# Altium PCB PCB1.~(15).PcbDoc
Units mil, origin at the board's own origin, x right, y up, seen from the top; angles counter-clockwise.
Board outline 5880 x 2260 mil, 2 copper layers (Top Layer, Bottom Layer); 100 components, 175 nets, 425 pads, 117 vias.
Unrouted connection lines stored in the file: 20.
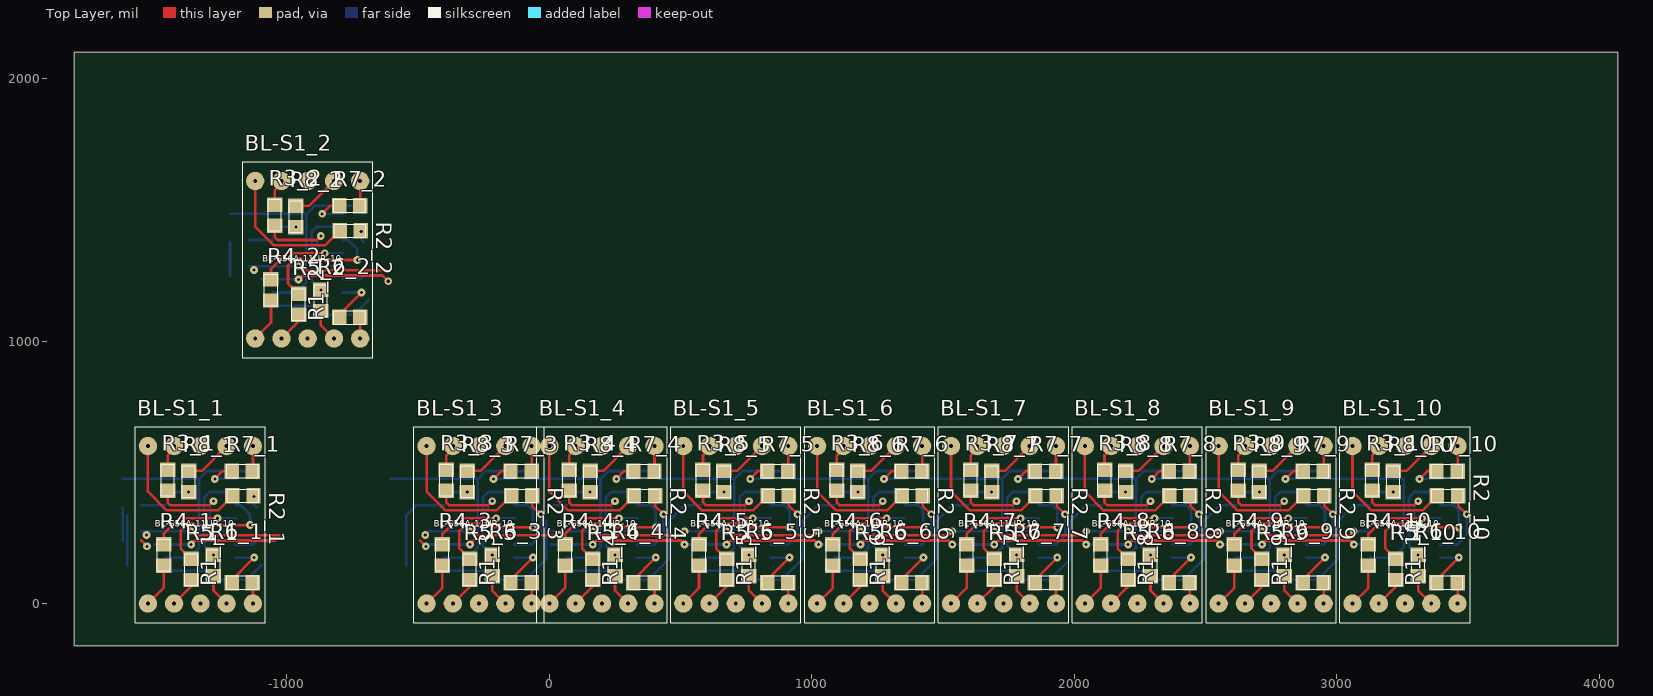
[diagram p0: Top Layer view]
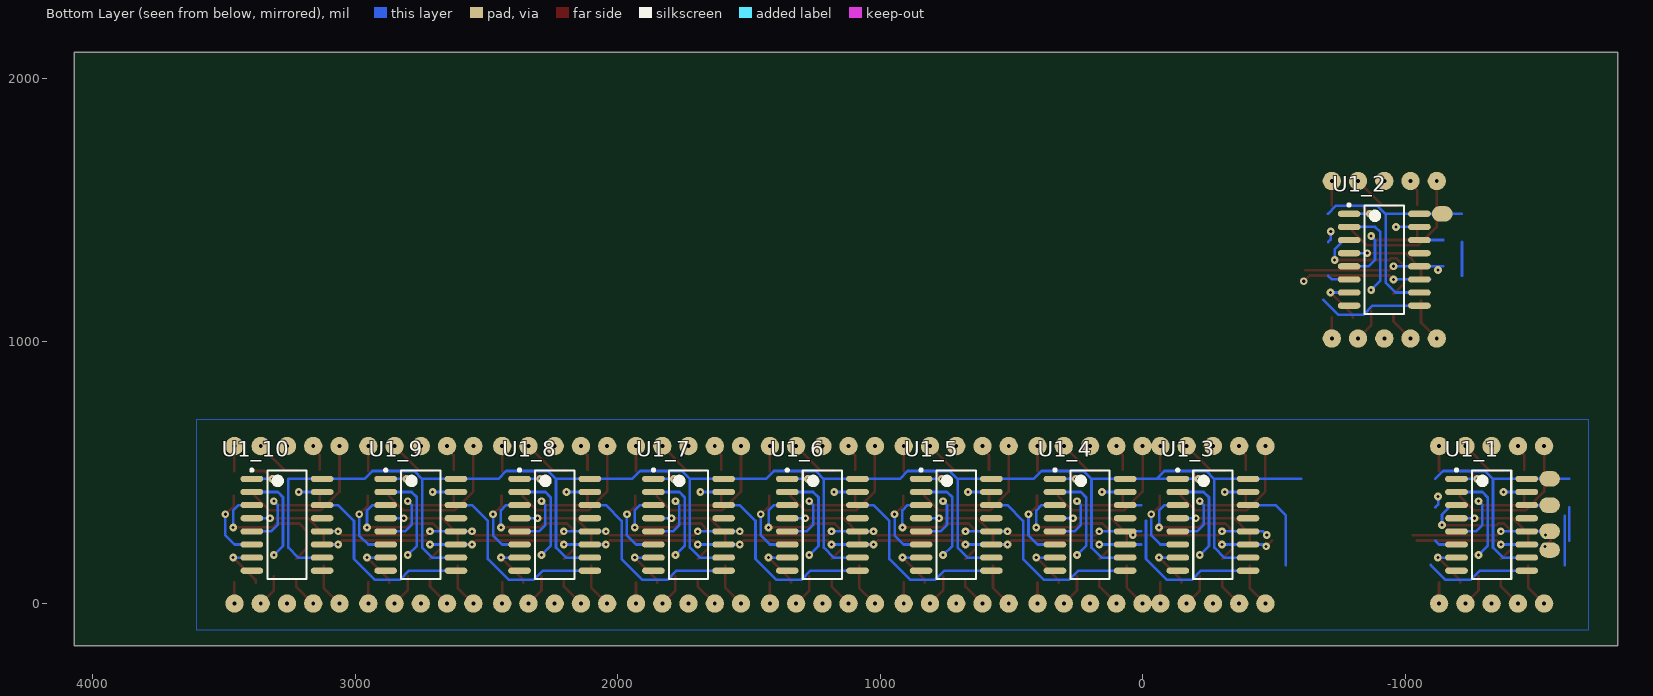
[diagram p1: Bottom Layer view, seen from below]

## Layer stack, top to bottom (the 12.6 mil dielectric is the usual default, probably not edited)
Top Solder: solder mask 0.4, Solder Resist, Dk 3.5
Top Layer: signal copper 1.4
Dielectric 1: dielectric 12.6, FR-4, Dk 4.8
Bottom Layer: signal copper 1.4
Bottom Solder: solder mask 0.4, Solder Resist, Dk 3.5

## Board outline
-1810,-160 -1810,2100 4070,2100 4070,-160 -220,-160

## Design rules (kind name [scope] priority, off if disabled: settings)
Clearance [All] p1: gap=5
MinimumSolderMaskSliver [All] p1 off: minsoldermaskwidth=10
PolygonConnect [All] p1: connectstyle=Relief reliefconductorwidth=10 reliefentries=4 polygonreliefangle="90 Angle" airgapwidth=15
RoomDefinition 10 [InComponentClass('10')] p1: confinementstyle=ConfineIn formatcopy=TRUE lockcomponents=FALSE outline 3005,-100 3600,-100 3600,700 3005,700
RoomDefinition 9 [InComponentClass('9')] p2: confinementstyle=ConfineIn formatcopy=TRUE lockcomponents=FALSE outline 2495,-100 3090,-100 3090,700 2495,700
RoomDefinition 8 [InComponentClass('8')] p3: confinementstyle=ConfineIn formatcopy=TRUE lockcomponents=FALSE outline 1985,-100 2580,-100 2580,700 1985,700
RoomDefinition 7 [InComponentClass('7')] p4: confinementstyle=ConfineIn formatcopy=TRUE lockcomponents=FALSE outline 1475,-100 2070,-100 2070,700 1475,700
RoomDefinition 6 [InComponentClass('6')] p5: confinementstyle=ConfineIn formatcopy=TRUE lockcomponents=FALSE outline 965,-100 1560,-100 1560,700 965,700
RoomDefinition 5 [InComponentClass('5')] p6: confinementstyle=ConfineIn formatcopy=TRUE lockcomponents=FALSE outline 455,-100 1050,-100 1050,700 455,700
RoomDefinition 4 [InComponentClass('4')] p7: confinementstyle=ConfineIn formatcopy=TRUE lockcomponents=FALSE outline -55,-100 540,-100 540,700 -55,700
RoomDefinition 2 [InComponentClass('2')] p8: confinementstyle=ConfineIn formatcopy=TRUE lockcomponents=FALSE outline -1218,910 -581,910 -581,1710 -1218,1710
RoomDefinition 1 [InComponentClass('1')] p9: confinementstyle=ConfineIn formatcopy=TRUE lockcomponents=FALSE outline -1627,-100 -990,-100 -990,700 -1627,700
RoomDefinition 3 [InComponentClass('3')] p10: confinementstyle=ConfineIn formatcopy=TRUE lockcomponents=FALSE outline -565,-100 72,-100 72,700 -565,700
RoutingVias [All] p1: holewidth=11.81 width=29.53 viastyle="Through Hole" minholewidth=11.81 minwidth=29.53 maxholewidth=28 maxwidth=70
SilkToBoardRegionClearance [All] p1 off:
SilkToSilkClearance [All] p1 off: silktosilkclearance=10
SilkToSolderMaskClearance [IsPad] p1 off: minsilkscreentomaskgap=10 clearancetoexposedcopper=TRUE
SolderMaskExpansion [All] p1: expansion=4
Width [All] p1: maxlimit=10 minlimit=7.87 preferedwidth=10
26 further rules are at their usual default settings.

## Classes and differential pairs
component class 6: BL-S1_6 R1_6 R2_6 R3_6 R4_6 R5_6 R6_6 R7_6 R8_6 U1_6
component class 5: BL-S1_5 R1_5 R2_5 R3_5 R4_5 R5_5 R6_5 R7_5 R8_5 U1_5
component class 1: BL-S1_1 R1_1 R2_1 R3_1 R4_1 R5_1 R6_1 R7_1 R8_1 U1_1
component class 2: BL-S1_2 R1_2 R2_2 R3_2 R4_2 R5_2 R6_2 R7_2 R8_2 U1_2
component class 3: BL-S1_3 R1_3 R2_3 R3_3 R4_3 R5_3 R6_3 R7_3 R8_3 U1_3
component class 4: BL-S1_4 R1_4 R2_4 R3_4 R4_4 R5_4 R6_4 R7_4 R8_4 U1_4
channel class Sheet2: 1 2 3 4 5 6 7 8 9 10
component class 7: BL-S1_7 R1_7 R2_7 R3_7 R4_7 R5_7 R6_7 R7_7 R8_7 U1_7
component class 8: BL-S1_8 R1_8 R2_8 R3_8 R4_8 R5_8 R6_8 R7_8 R8_8 U1_8
component class 9: BL-S1_9 R1_9 R2_9 R3_9 R4_9 R5_9 R6_9 R7_9 R8_9 U1_9
component class 10: BL-S1_10 R1_10 R2_10 R3_10 R4_10 R5_10 R6_10 R7_10 R8_10 U1_10

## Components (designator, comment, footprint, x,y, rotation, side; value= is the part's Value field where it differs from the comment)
BL-S1_1 "BL-S56A-11UR" BL-S56A-11UR -1578.03,300 r0 top locked (schematic designator BL-S1)
BL-S1_2 "BL-S56A-11UR" BL-S56A-11UR -1169.03,1310 r0 top (schematic designator BL-S1)
BL-S1_3 "BL-S56A-11UR" BL-S56A-11UR -516.03,300 r0 top (schematic designator BL-S1)
BL-S1_4 "BL-S56A-11UR" BL-S56A-11UR -48.03,300 r0 top (schematic designator BL-S1)
BL-S1_5 "BL-S56A-11UR" BL-S56A-11UR 461.97,300 r0 top (schematic designator BL-S1)
BL-S1_6 "BL-S56A-11UR" BL-S56A-11UR 971.97,300 r0 top (schematic designator BL-S1)
BL-S1_7 "BL-S56A-11UR" BL-S56A-11UR 1481.97,300 r0 top (schematic designator BL-S1)
BL-S1_8 "BL-S56A-11UR" BL-S56A-11UR 1991.97,300 r0 top (schematic designator BL-S1)
BL-S1_9 "BL-S56A-11UR" BL-S56A-11UR 2501.97,300 r0 top (schematic designator BL-S1)
BL-S1_10 "BL-S56A-11UR" BL-S56A-11UR 3011.97,300 r0 top (schematic designator BL-S1)
R1_1 "310R" Res0805 -1170,80 r180 top (schematic designator R1)
R1_2 "310R" Res0805 -761,1090 r180 top (schematic designator R1)
R1_3 "310R" Res0805 -108,80 r180 top (schematic designator R1)
R1_4 "310R" Res0805 360,80 r180 top (schematic designator R1)
R1_5 "310R" Res0805 870,80 r180 top (schematic designator R1)
R1_6 "310R" Res0805 1380,80 r180 top (schematic designator R1)
R1_7 "310R" Res0805 1890,80 r180 top (schematic designator R1)
R1_8 "310R" Res0805 2400,80 r180 top (schematic designator R1)
R1_9 "310R" Res0805 2910,80 r180 top (schematic designator R1)
R1_10 "310R" Res0805 3420,80 r180 top (schematic designator R1)
R2_1 "310R" Res0805 -1167.95,410 r0 top (schematic designator R2)
R2_2 "310R" Res0805 -758.95,1420 r0 top (schematic designator R2)
R2_3 "310R" Res0805 -105.95,410 r0 top (schematic designator R2)
R2_4 "310R" Res0805 362.05,410 r0 top (schematic designator R2)
R2_5 "310R" Res0805 872.05,410 r0 top (schematic designator R2)
R2_6 "310R" Res0805 1382.05,410 r0 top (schematic designator R2)
R2_7 "310R" Res0805 1892.05,410 r0 top (schematic designator R2)
R2_8 "310R" Res0805 2402.05,410 r0 top (schematic designator R2)
R2_9 "310R" Res0805 2912.05,410 r0 top (schematic designator R2)
R2_10 "310R" Res0805 3422.05,410 r0 top (schematic designator R2)
R3_1 "310R" Res0805 -1455,470 r270 top (schematic designator R3)
R3_2 "310R" Res0805 -1046,1480 r270 top (schematic designator R3)
R3_3 "310R" Res0805 -393,470 r270 top (schematic designator R3)
R3_4 "310R" Res0805 75,470 r270 top (schematic designator R3)
R3_5 "310R" Res0805 585,470 r270 top (schematic designator R3)
R3_6 "310R" Res0805 1095,470 r270 top (schematic designator R3)
R3_7 "310R" Res0805 1605,470 r270 top (schematic designator R3)
R3_8 "310R" Res0805 2115,470 r270 top (schematic designator R3)
R3_9 "310R" Res0805 2625,470 r270 top (schematic designator R3)
R3_10 "310R" Res0805 3135,470 r270 top (schematic designator R3)
R4_1 "310R" Res0805 -1470,185 r90 top (schematic designator R4)
R4_2 "310R" Res0805 -1061,1195 r90 top (schematic designator R4)
R4_3 "310R" Res0805 -408,185 r90 top (schematic designator R4)
R4_4 "310R" Res0805 60,185 r90 top (schematic designator R4)
R4_5 "310R" Res0805 570,185 r90 top (schematic designator R4)
R4_6 "310R" Res0805 1080,185 r90 top (schematic designator R4)
R4_7 "310R" Res0805 1590,185 r90 top (schematic designator R4)
R4_8 "310R" Res0805 2100,185 r90 top (schematic designator R4)
R4_9 "310R" Res0805 2610,185 r90 top (schematic designator R4)
R4_10 "310R" Res0805 3120,185 r90 top (schematic designator R4)
R5_1 "310R" Res0805 -1365,130 r90 top (schematic designator R5)
R5_2 "310R" Res0805 -956,1140 r90 top (schematic designator R5)
R5_3 "310R" Res0805 -303,130 r90 top (schematic designator R5)
R5_4 "310R" Res0805 165,130 r90 top (schematic designator R5)
R5_5 "310R" Res0805 675,130 r90 top (schematic designator R5)
R5_6 "310R" Res0805 1185,130 r90 top (schematic designator R5)
R5_7 "310R" Res0805 1695,130 r90 top (schematic designator R5)
R5_8 "310R" Res0805 2205,130 r90 top (schematic designator R5)
R5_9 "310R" Res0805 2715,130 r90 top (schematic designator R5)
R5_10 "310R" Res0805 3225,130 r90 top (schematic designator R5)
R6_1 "310R" Res0805 -1280,145 r90 top (schematic designator R6)
R6_2 "310R" Res0805 -871,1155 r90 top (schematic designator R6)
R6_3 "310R" Res0805 -218,145 r90 top (schematic designator R6)
R6_4 "310R" Res0805 250,145 r90 top (schematic designator R6)
R6_5 "310R" Res0805 760,145 r90 top (schematic designator R6)
R6_6 "310R" Res0805 1270,145 r90 top (schematic designator R6)
R6_7 "310R" Res0805 1780,145 r90 top (schematic designator R6)
R6_8 "310R" Res0805 2290,145 r90 top (schematic designator R6)
R6_9 "310R" Res0805 2800,145 r90 top (schematic designator R6)
R6_10 "310R" Res0805 3310,145 r90 top (schematic designator R6)
R7_1 "310R" Res0805 -1170,505 r180 top (schematic designator R7)
R7_2 "310R" Res0805 -761,1515 r180 top (schematic designator R7)
R7_3 "310R" Res0805 -108,505 r180 top (schematic designator R7)
R7_4 "310R" Res0805 360,505 r180 top (schematic designator R7)
R7_5 "310R" Res0805 870,505 r180 top (schematic designator R7)
R7_6 "310R" Res0805 1380,505 r180 top (schematic designator R7)
R7_7 "310R" Res0805 1890,505 r180 top (schematic designator R7)
R7_8 "310R" Res0805 2400,505 r180 top (schematic designator R7)
R7_9 "310R" Res0805 2910,505 r180 top (schematic designator R7)
R7_10 "310R" Res0805 3420,505 r180 top (schematic designator R7)
R8_1 "310R" Res0805 -1375,465 r270 top (schematic designator R8)
R8_2 "310R" Res0805 -966,1475 r270 top (schematic designator R8)
R8_3 "310R" Res0805 -313,465 r270 top (schematic designator R8)
R8_4 "310R" Res0805 155,465 r270 top (schematic designator R8)
R8_5 "310R" Res0805 665,465 r270 top (schematic designator R8)
R8_6 "310R" Res0805 1175,465 r270 top (schematic designator R8)
R8_7 "310R" Res0805 1685,465 r270 top (schematic designator R8)
R8_8 "310R" Res0805 2195,465 r270 top (schematic designator R8)
R8_9 "310R" Res0805 2705,465 r270 top (schematic designator R8)
R8_10 "310R" Res0805 3215,465 r270 top (schematic designator R8)
U1_1 "HD74HC595FP" PRSP0016DH-B_N -1330,300 r180 bottom (schematic designator U1)
U1_2 "HD74HC595FP" PRSP0016DH-B_N -921,1310 r180 bottom (schematic designator U1)
U1_3 "HD74HC595FP" PRSP0016DH-B_N -268,300 r180 bottom (schematic designator U1)
U1_4 "HD74HC595FP" PRSP0016DH-B_N 200,300 r180 bottom (schematic designator U1)
U1_5 "HD74HC595FP" PRSP0016DH-B_N 710,300 r180 bottom (schematic designator U1)
U1_6 "HD74HC595FP" PRSP0016DH-B_N 1220,300 r180 bottom (schematic designator U1)
U1_7 "HD74HC595FP" PRSP0016DH-B_N 1730,300 r180 bottom (schematic designator U1)
U1_8 "HD74HC595FP" PRSP0016DH-B_N 2240,300 r180 bottom (schematic designator U1)
U1_9 "HD74HC595FP" PRSP0016DH-B_N 2750,300 r180 bottom (schematic designator U1)
U1_10 "HD74HC595FP" PRSP0016DH-B_N 3260,300 r180 bottom (schematic designator U1)

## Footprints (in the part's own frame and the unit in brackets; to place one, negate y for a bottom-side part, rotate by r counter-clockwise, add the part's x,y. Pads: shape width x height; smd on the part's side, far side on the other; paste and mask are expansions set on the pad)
BL-S56A-11UR [mil]
  round 70 hole 15: 1(48.03,-300) 2(148.03,-300) 3(248.03,-300) 4(348.03,-300) 5(448.03,-300) 6(448.03,300) 7(348.03,300) 8(248.03,300) 9(148.03,300) 10(48.03,300)
  silkscreen extent 0,-374 496,374, body extent 0,-374 496,374, height 315
PRSP0016DH-B_N [mm] "SOP, 16-Leads, Body 10.06x5.5mm, Pitch 1.27mm, IPC Medium Density"
  oval 2.2x0.6 smd: 1(-3.4,4.445) 2(-3.4,3.175) 3(-3.4,1.905) 4(-3.4,0.635) 5(-3.4,-0.635) 6(-3.4,-1.905) 7(-3.4,-3.175) 8(-3.4,-4.445) 9(3.4,-4.445) 10(3.4,-3.175) 11(3.4,-1.905) 12(3.4,-0.635) 13(3.4,0.635) 14(3.4,1.905) 15(3.4,3.175) 16(3.4,4.445)
  silkscreen extent -3.52,-5.25 1.9,5.42, body extent -2.7,-5.25 2.7,5.25, height 2.2
Res0805 [mm]
  rect 1.4x1.5 smd: 1(-1.025,0) 2(1.025,0)
  silkscreen extent -1.52,-0.64 1.52,0.64, body extent -1.15,-0.67 1.15,0.68, height 0.76

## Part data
BL-S1_1 BL-S1_2 BL-S1_3 BL-S1_4 BL-S1_5 BL-S1_6 BL-S1_7 BL-S1_8 BL-S1_9 BL-S1_10: library part Component_1
R1_1 R1_2 R1_3 R1_4 R1_5 R1_6 R1_7 R1_8 R1_9 R1_10 R2_1 R2_2 R2_3 R2_4 R2_5 R2_6 R2_7 R2_8 R2_9 R2_10 R3_1 R3_2 R3_3 R3_4 R3_5 R3_6 R3_7 R3_8 R3_9 R3_10 R4_1 R4_2 R4_3 R4_4 R4_5 R4_6 R4_7 R4_8 R4_9 R4_10 R5_1 R5_2 R5_3 R5_4 R5_5 R5_6 R5_7 R5_8 R5_9 R5_10 R6_1 R6_2 R6_3 R6_4 R6_5 R6_6 R6_7 R6_8 R6_9 R6_10 R7_1 R7_2 R7_3 R7_4 R7_5 R7_6 R7_7 R7_8 R7_9 R7_10 R8_1 R8_2 R8_3 R8_4 R8_5 R8_6 R8_7 R8_8 R8_9 R8_10: library part Res1, "Resistor"
U1_1 U1_2 U1_3 U1_4 U1_5 U1_6 U1_7 U1_8 U1_9 U1_10: "8-bit Shift Register / Latch with 3-State Outputs"

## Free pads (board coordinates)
  oval 78.74x59.06 smd far side: 8(-1550.94,475) 8(-1141.94,1485) 9(-1550.94,375) 10(-1550.94,275) 11(-1551,204)

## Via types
v1: diameter 29.53, hole 11.81, Top Layer to Bottom Layer, tented both sides, 90 vias
v2: diameter 29.53, hole 11.81, Top Layer to Bottom Layer, 27 vias

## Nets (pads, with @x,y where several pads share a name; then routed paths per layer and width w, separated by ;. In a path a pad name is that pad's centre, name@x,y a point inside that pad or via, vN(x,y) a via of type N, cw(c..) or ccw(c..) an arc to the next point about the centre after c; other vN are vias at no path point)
+5V: pad.8 U1_1.10 U1_1.16 U1_2.10 U1_2.16 U1_3.10 U1_3.16 U1_4.10 U1_4.16 U1_5.10 U1_5.16 U1_6.10 U1_6.16 U1_7.10 U1_7.16 U1_8.10 U1_8.16 U1_9.10 U1_9.16 U1_10.10 U1_10.16 | length 9592.6
  Bottom Layer w10: -1625,475 U1_1.16 ; -1595,475 U1_1.16 ; U1_1.10 -1372.91,175 -1335.24,212.67 -1335.24,475 ; -1216,1485 U1_2.16 ; -1186,1485 U1_2.16 ; -1115,475 -1145,505 -1305,505 -1335,475 U1_1.16 ; U1_2.10 -963.91,1185 -926.24,1222.67 -926.24,1485 ; -706,1485 -736,1515 -896,1515 -926,1485 U1_2.16 ; -605,475 U1_3.16@-443.86,475 ; -563,475 U1_3.16 -273,475 -243,505 -83,505 -53,475 ; U1_3.10 -310.91,175 -273.24,212.67 -273.24,475 ; -95,475 U1_4.16 194.76,475 ; U1_4.10 157.09,175 194.76,212.67 194.76,475 ; U1_5.10 667.09,175 704.76,212.67 704.76,475 ; U1_6.10 1177.09,175 1214.76,212.67 1214.76,475 ; U1_7.10 1687.09,175 1724.76,212.67 1724.76,475 ; U1_8.10 2197.09,175 2234.76,212.67 2234.76,475 ; U1_9.10 2707.09,175 2744.76,212.67 2744.76,475 ; U1_10.10 3217.09,175 3254.76,212.67 3254.76,475 ; 3255,475 3254.76,475 ; 194.76,475 195,475 225,505 385,505 415,475 U1_5.16 704.76,475 ; 704.76,475 705,475 735,505 895,505 925,475 U1_6.16 1214.76,475 ; 1214.76,475 1215,475 1245,505 1405,505 1435,475 U1_7.16 1724.76,475 ; 1724.76,475 1725,475 1755,505 1915,505 1945,475 U1_8.16 2234.76,475 ; 2234.76,475 2235,475 2265,505 2425,505 2455,475 U1_9.16 2744.76,475 ; 2744.76,475 2745,475 2775,505 2935,505 2965,475 U1_10.16 3254.76,475
GND: BL-S1_1.3 BL-S1_1.8 BL-S1_2.3 BL-S1_2.8 BL-S1_3.3 BL-S1_3.8 BL-S1_4.3 BL-S1_4.8 BL-S1_5.3 BL-S1_5.8 BL-S1_6.3 BL-S1_6.8 BL-S1_7.3 BL-S1_7.8 BL-S1_8.3 BL-S1_8.8 BL-S1_9.3 BL-S1_9.8 BL-S1_10.3 BL-S1_10.8 U1_1.8 U1_1.13 U1_2.8 U1_2.13 U1_3.8 U1_3.13 U1_4.8 U1_4.13 U1_5.8 U1_5.13 U1_6.8 U1_6.13 U1_7.8 U1_7.13 U1_8.8 U1_8.13 U1_9.8 U1_9.13 U1_10.8 U1_10.13
L_A_1: BL-S1_1.7 R8_1.1 | length 184.2
  Top Layer w10: R8_1.1 -1324.65,505.35 BL-S1_1.7
L_A_2: BL-S1_2.7 R8_2.1 | length 184.2
  Top Layer w10: R8_2.1 -915.65,1515.35 BL-S1_2.7
L_A_3: BL-S1_3.7 R8_3.1 | length 184.2
  Top Layer w10: R8_3.1 -262.65,505.35 BL-S1_3.7
L_A_4: BL-S1_4.7 R8_4.1 | length 184.2
  Top Layer w10: R8_4.1 205.35,505.35 BL-S1_4.7
L_A_5: BL-S1_5.7 R8_5.1 | length 184.2
  Top Layer w10: R8_5.1 715.36,505.35 BL-S1_5.7
L_A_6: BL-S1_6.7 R8_6.1 | length 368.4
  Top Layer w10: 1225.36,505.35 R8_6.1 1225.36,505.35 ; 1225.36,505.35 BL-S1_6.7 1225.36,505.35
L_A_7: BL-S1_7.7 R8_7.1 | length 184.2
  Top Layer w10: R8_7.1 1735.36,505.35 BL-S1_7.7
L_A_8: BL-S1_8.7 R8_8.1 | length 184.2
  Top Layer w10: R8_8.1 2245.36,505.35 BL-S1_8.7
L_A_9: BL-S1_9.7 R8_9.1 | length 184.2
  Top Layer w10: R8_9.1 2755.36,505.35 BL-S1_9.7
L_A_10: BL-S1_10.7 R8_10.1 | length 184.2
  Top Layer w10: R8_10.1 3265.36,505.35 BL-S1_10.7
L_B_1: BL-S1_1.6 R7_1.1 | length 95.1
  Top Layer w10: BL-S1_1.6 -1129.65,599.65 R7_1.1
L_B_2: BL-S1_2.6 R7_2.1 | length 95.1
  Top Layer w10: BL-S1_2.6 -720.65,1609.65 R7_2.1
L_B_3: BL-S1_3.6 R7_3.1 | length 95.1
  Top Layer w10: BL-S1_3.6 -67.65,599.65 R7_3.1
L_B_4: BL-S1_4.6 R7_4.1 | length 95.1
  Top Layer w10: BL-S1_4.6 400.35,599.65 R7_4.1
L_B_5: BL-S1_5.6 R7_5.1 | length 95.1
  Top Layer w10: BL-S1_5.6 910.35,599.65 R7_5.1
L_B_6: BL-S1_6.6 R7_6.1 | length 190.3
  Top Layer w10: BL-S1_6.6@1420.35,599.65 R7_6.1 BL-S1_6.6@1420.35,599.65 ; BL-S1_6.6@1420.35,599.65 BL-S1_6.6 BL-S1_6.6@1420.35,599.65
L_B_7: BL-S1_7.6 R7_7.1 | length 95.1
  Top Layer w10: BL-S1_7.6 1930.35,599.65 R7_7.1
L_B_8: BL-S1_8.6 R7_8.1 | length 95.1
  Top Layer w10: BL-S1_8.6 2440.35,599.65 R7_8.1
L_B_9: BL-S1_9.6 R7_9.1 | length 95.1
  Top Layer w10: BL-S1_9.6 2950.35,599.65 R7_9.1
L_B_10: BL-S1_10.6 R7_10.1 | length 95.1
  Top Layer w10: BL-S1_10.6 3460.35,599.65 R7_10.1
L_C_1: BL-S1_1.4 R6_1.1 | length 125.4
  Top Layer w10: R6_1.1 -1280,50 BL-S1_1.4
L_C_2: BL-S1_2.4 R6_2.1 | length 125.4
  Top Layer w10: R6_2.1 -871,1060 BL-S1_2.4
L_C_3: BL-S1_3.4 R6_3.1 | length 125.4
  Top Layer w10: R6_3.1 -218,50 BL-S1_3.4
L_C_4: BL-S1_4.4 R6_4.1 | length 125.4
  Top Layer w10: R6_4.1 250,50 BL-S1_4.4
L_C_5: BL-S1_5.4 R6_5.1 | length 125.4
  Top Layer w10: R6_5.1 760,50 BL-S1_5.4
L_C_6: BL-S1_6.4 R6_6.1 | length 250.7
  Top Layer w10: 1270,50 R6_6.1 1270,50 ; 1270,50 BL-S1_6.4 1270,50
L_C_7: BL-S1_7.4 R6_7.1 | length 125.4
  Top Layer w10: R6_7.1 1780,50 BL-S1_7.4
L_C_8: BL-S1_8.4 R6_8.1 | length 125.4
  Top Layer w10: R6_8.1 2290,50 BL-S1_8.4
L_C_9: BL-S1_9.4 R6_9.1 | length 125.4
  Top Layer w10: R6_9.1 2800,50 BL-S1_9.4
L_C_10: BL-S1_10.4 R6_10.1 | length 125.4
  Top Layer w10: R6_10.1 3310,50 BL-S1_10.4
L_D_1: BL-S1_1.2 R5_1.1 | length 111.6
  Top Layer w10: BL-S1_1.2 -1365,65 R5_1.1@-1365,84.65
L_D_2: BL-S1_2.2 R5_2.1 | length 111.6
  Top Layer w10: BL-S1_2.2 -956,1075 R5_2.1@-956,1094.65
L_D_3: BL-S1_3.2 R5_3.1 | length 111.6
  Top Layer w10: BL-S1_3.2 -303,65 R5_3.1@-303,84.65
L_D_4: BL-S1_4.2 R5_4.1 | length 111.6
  Top Layer w10: BL-S1_4.2 165,65 R5_4.1@165,84.65
L_D_5: BL-S1_5.2 R5_5.1 | length 111.6
  Top Layer w10: BL-S1_5.2 675,65 R5_5.1@675,84.65
L_D_6: BL-S1_6.2 R5_6.1 | length 223.1
  Top Layer w10: R5_6.1@1185,65 BL-S1_6.2 R5_6.1@1185,65 ; R5_6.1@1185,65 1185,84.65 R5_6.1@1185,65
L_D_7: BL-S1_7.2 R5_7.1 | length 111.6
  Top Layer w10: BL-S1_7.2 1695,65 R5_7.1@1695,84.65
L_D_8: BL-S1_8.2 R5_8.1 | length 111.6
  Top Layer w10: BL-S1_8.2 2205,65 R5_8.1@2205,84.65
L_D_9: BL-S1_9.2 R5_9.1 | length 111.6
  Top Layer w10: BL-S1_9.2 2715,65 R5_9.1@2715,84.65
L_D_10: BL-S1_10.2 R5_10.1 | length 111.6
  Top Layer w10: BL-S1_10.2 3225,65 R5_10.1@3225,84.65
L_E_1: BL-S1_1.1 R4_1.1 | length 169.5
  Top Layer w10: BL-S1_1.1 -1470,60 R4_1.1
L_E_2: BL-S1_2.1 R4_2.1 | length 169.5
  Top Layer w10: BL-S1_2.1 -1061,1070 R4_2.1
L_E_3: BL-S1_3.1 R4_3.1 | length 169.5
  Top Layer w10: BL-S1_3.1 -408,60 R4_3.1
L_E_4: BL-S1_4.1 R4_4.1 | length 169.5
  Top Layer w10: BL-S1_4.1 60,60 R4_4.1
L_E_5: BL-S1_5.1 R4_5.1 | length 169.5
  Top Layer w10: BL-S1_5.1 570,60 R4_5.1
L_E_6: BL-S1_6.1 R4_6.1 | length 339
  Top Layer w10: 1080,60 BL-S1_6.1 1080,60 ; 1080,60 R4_6.1 1080,60
L_E_7: BL-S1_7.1 R4_7.1 | length 169.5
  Top Layer w10: BL-S1_7.1 1590,60 R4_7.1
L_E_8: BL-S1_8.1 R4_8.1 | length 169.5
  Top Layer w10: BL-S1_8.1 2100,60 R4_8.1
L_E_9: BL-S1_9.1 R4_9.1 | length 169.5
  Top Layer w10: BL-S1_9.1 2610,60 R4_9.1
L_E_10: BL-S1_10.1 R4_10.1 | length 169.5
  Top Layer w10: BL-S1_10.1 3120,60 R4_10.1
L_F_1: BL-S1_1.9 R3_1.1 | length 100
  Top Layer w10: R3_1.1 -1455,565 -1430,590 BL-S1_1.9
L_F_2: BL-S1_2.9 R3_2.1 | length 100
  Top Layer w10: R3_2.1 -1046,1575 -1021,1600 BL-S1_2.9
L_F_3: BL-S1_3.9 R3_3.1 | length 100
  Top Layer w10: R3_3.1 -393,565 -368,590 BL-S1_3.9
L_F_4: BL-S1_4.9 R3_4.1 | length 100
  Top Layer w10: R3_4.1 75,565 100,590 BL-S1_4.9
L_F_5: BL-S1_5.9 R3_5.1 | length 100
  Top Layer w10: R3_5.1 585,565 610,590 BL-S1_5.9
L_F_6: BL-S1_6.9 R3_6.1 | length 200
  Top Layer w10: 1095,565 R3_6.1 1095,565 ; 1095,565 BL-S1_6.9@1120,590 ; 1095,565 BL-S1_6.9@1120,590 ; BL-S1_6.9@1120,590 BL-S1_6.9 BL-S1_6.9@1120,590
L_F_7: BL-S1_7.9 R3_7.1 | length 100
  Top Layer w10: R3_7.1 1605,565 1630,590 BL-S1_7.9
L_F_8: BL-S1_8.9 R3_8.1 | length 100
  Top Layer w10: R3_8.1 2115,565 2140,590 BL-S1_8.9
L_F_9: BL-S1_9.9 R3_9.1 | length 100
  Top Layer w10: R3_9.1 2625,565 2650,590 BL-S1_9.9
L_F_10: BL-S1_10.9 R3_10.1 | length 100
  Top Layer w10: R3_10.1 3135,565 3160,590 BL-S1_10.9
L_G_1: BL-S1_1.10 R2_1.1 | length 547.9
  Top Layer w10: BL-S1_1.10 -1530,426.35 -1458.42,354.76 -1263.54,354.76 R2_1.1
L_G_2: BL-S1_2.10 R2_2.1 | length 547.9
  Top Layer w10: BL-S1_2.10 -1121,1436.35 -1049.42,1364.76 -854.54,1364.76 R2_2.1
L_G_3: BL-S1_3.10 R2_3.1 | length 547.9
  Top Layer w10: BL-S1_3.10 -468,426.35 -396.42,354.76 -201.54,354.76 R2_3.1
L_G_4: BL-S1_4.10 R2_4.1 | length 547.9
  Top Layer w10: BL-S1_4.10 0,426.35 71.58,354.76 266.46,354.76 R2_4.1
L_G_5: BL-S1_5.10 R2_5.1 | length 547.9
  Top Layer w10: BL-S1_5.10 510,426.35 581.58,354.76 776.46,354.76 R2_5.1
L_G_6: BL-S1_6.10 R2_6.1 | length 1095.8
  Top Layer w10: 1020,426.35 1091.58,354.76 ; 1020,426.35 BL-S1_6.10 1020,426.35 ; 1020,426.35 1091.58,354.76 ; 1091.58,354.76 1286.46,354.76 ; 1091.58,354.76 1286.46,354.76 ; 1286.46,354.76 R2_6.1 1286.46,354.76
L_G_7: BL-S1_7.10 R2_7.1 | length 547.9
  Top Layer w10: BL-S1_7.10 1530,426.35 1601.58,354.76 1796.46,354.76 R2_7.1
L_G_8: BL-S1_8.10 R2_8.1 | length 547.9
  Top Layer w10: BL-S1_8.10 2040,426.35 2111.58,354.76 2306.46,354.76 R2_8.1
L_G_9: BL-S1_9.10 R2_9.1 | length 547.9
  Top Layer w10: BL-S1_9.10 2550,426.35 2621.58,354.76 2816.46,354.76 R2_9.1
L_G_10: BL-S1_10.10 R2_10.1 | length 547.9
  Top Layer w10: BL-S1_10.10 3060,426.35 3131.58,354.76 3326.46,354.76 R2_10.1
L_H_1: BL-S1_1.5 R1_1.1 | length 80.1
  Top Layer w10: BL-S1_1.5 -1129.65,0.35 R1_1.1
L_H_2: BL-S1_2.5 R1_2.1 | length 80.1
  Top Layer w10: BL-S1_2.5 -720.65,1010.35 R1_2.1
L_H_3: BL-S1_3.5 R1_3.1 | length 80.1
  Top Layer w10: BL-S1_3.5 -67.65,0.35 R1_3.1
L_H_4: BL-S1_4.5 R1_4.1 | length 80.1
  Top Layer w10: BL-S1_4.5 400.35,0.35 R1_4.1
L_H_5: BL-S1_5.5 R1_5.1 | length 80.1
  Top Layer w10: BL-S1_5.5 910.35,0.35 R1_5.1
L_H_6: BL-S1_6.5 R1_6.1 | length 160.3
  Top Layer w10: BL-S1_6.5@1420.35,0.35 BL-S1_6.5 BL-S1_6.5@1420.35,0.35 ; BL-S1_6.5@1420.35,0.35 R1_6.1 BL-S1_6.5@1420.35,0.35
L_H_7: BL-S1_7.5 R1_7.1 | length 80.1
  Top Layer w10: BL-S1_7.5 1930.35,0.35 R1_7.1
L_H_8: BL-S1_8.5 R1_8.1 | length 80.1
  Top Layer w10: BL-S1_8.5 2440.35,0.35 R1_8.1
L_H_9: BL-S1_9.5 R1_9.1 | length 80.1
  Top Layer w10: BL-S1_9.5 2950.35,0.35 R1_9.1
L_H_10: BL-S1_10.5 R1_10.1 | length 80.1
  Top Layer w10: BL-S1_10.5 3460.35,0.35 R1_10.1
NetR1_1_2: R1_1.2 U1_1.7 | length 201.5
  Top Layer w10: R1_1.2 -1210.35,89.65 v1(-1125,175)
  Bottom Layer w10: U1_1.7 v1(-1125,175)
NetR1_2_2: R1_2.2 U1_2.7 | length 201.5
  Top Layer w10: R1_2.2 -801.35,1099.65 v1(-716,1185)
  Bottom Layer w10: U1_2.7 v1(-716,1185)
NetR1_3_2: R1_3.2 U1_3.7 | length 201.5
  Top Layer w10: R1_3.2 -148.36,89.65 v1(-63,175)
  Bottom Layer w10: U1_3.7 v1(-63,175)
NetR1_4_2: R1_4.2 U1_4.7 | length 201.5
  Top Layer w10: R1_4.2 319.65,89.65 v1(405,175)
  Bottom Layer w10: U1_4.7 v1(405,175)
NetR1_5_2: R1_5.2 U1_5.7 | length 201.5
  Top Layer w10: R1_5.2 829.65,89.65 v1(915,175)
  Bottom Layer w10: U1_5.7 v1(915,175)
NetR1_6_2: R1_6.2 U1_6.7 | length 403
  Top Layer w10: R1_6.2@1339.65,89.65 v1(1425,175) R1_6.2@1339.65,89.65 ; R1_6.2@1339.65,89.65 R1_6.2 R1_6.2@1339.65,89.65
  Bottom Layer w10: U1_6.7 v1(1425,175) U1_6.7
NetR1_7_2: R1_7.2 U1_7.7 | length 201.5
  Top Layer w10: R1_7.2 1849.65,89.65 v1(1935,175)
  Bottom Layer w10: U1_7.7 v1(1935,175)
NetR1_8_2: R1_8.2 U1_8.7 | length 201.5
  Top Layer w10: R1_8.2 2359.65,89.65 v1(2445,175)
  Bottom Layer w10: U1_8.7 v1(2445,175)
NetR1_9_2: R1_9.2 U1_9.7 | length 201.5
  Top Layer w10: R1_9.2 2869.65,89.65 v1(2955,175)
  Bottom Layer w10: U1_9.7 v1(2955,175)
NetR1_10_2: R1_10.2 U1_10.7 | length 201.5
  Top Layer w10: R1_10.2 3379.65,89.65 v1(3465,175)
  Bottom Layer w10: U1_10.7 v1(3465,175)
NetR2_1_2: R2_1.2 U1_1.6 | length 258.9
  Bottom Layer w10: -1217.24,1248.76 -1217.24,1377.45 ; U1_1.6 -1130,225 -1116.24,238.76 ; v1(-1126,408) -1126,377.21 -1116.24,367.45
NetR2_2_2: R2_2.2 U1_2.6 | length 130.2
  Bottom Layer w10: U1_2.6 -721,1235 -707.24,1248.76 ; v1(-717,1418) -717,1387.21 -707.24,1377.45
NetR2_3_2: R2_3.2 U1_3.6 | length 278.9
  Top Layer w10: R2_3.2 -65.59,372.59 v1(-33.24,340.24)
  Bottom Layer w10: U1_3.6 -68,225 -33.24,259.76 v1(-33.24,340.24)
NetR2_4_2: R2_4.2 U1_4.6 | length 278.9
  Top Layer w10: R2_4.2 402.41,372.59 v1(434.76,340.24)
  Bottom Layer w10: U1_4.6 400,225 434.76,259.76 v1(434.76,340.24)
NetR2_5_2: R2_5.2 U1_5.6 | length 278.9
  Top Layer w10: R2_5.2 912.41,372.59 v1(944.76,340.24)
  Bottom Layer w10: U1_5.6 910,225 944.76,259.76 v1(944.76,340.24)
NetR2_6_2: R2_6.2 U1_6.6 | length 557.9
  Top Layer w10: 1422.41,372.59 R2_6.2 1422.41,372.59 ; 1422.41,372.59 v1(1454.76,340.24) 1422.41,372.59
  Bottom Layer w10: 1420,225 U1_6.6 1420,225 ; 1420,225 1454.76,259.76 ; 1420,225 1454.76,259.76 ; 1454.76,259.76 v1(1454.76,340.24) 1454.76,259.76
NetR2_7_2: R2_7.2 U1_7.6 | length 278.9
  Top Layer w10: R2_7.2 1932.41,372.59 v1(1964.76,340.24)
  Bottom Layer w10: U1_7.6 1930,225 1964.76,259.76 v1(1964.76,340.24)
NetR2_8_2: R2_8.2 U1_8.6 | length 278.9
  Top Layer w10: R2_8.2 2442.41,372.59 v1(2474.76,340.24)
  Bottom Layer w10: U1_8.6 2440,225 2474.76,259.76 v1(2474.76,340.24)
NetR2_9_2: R2_9.2 U1_9.6 | length 278.9
  Top Layer w10: R2_9.2 2952.41,372.59 v1(2984.76,340.24)
  Bottom Layer w10: U1_9.6 2950,225 2984.76,259.76 v1(2984.76,340.24)
NetR2_10_2: R2_10.2 U1_10.6 | length 278.9
  Top Layer w10: R2_10.2 3462.41,372.59 v1(3494.76,340.24)
  Bottom Layer w10: U1_10.6 3460,225 3494.76,259.76 v1(3494.76,340.24)
NetR3_1_2: R3_1.2 U1_1.5 | length 435.2
  Top Layer w10: R3_1.2 -1455,385 -1445,375 -1295,375 v1(-1280,390)
  Bottom Layer w10: v1(-1280,390) -1294.76,375.24 -1294.76,299.76 -1270,275 U1_1.5
NetR3_2_2: R3_2.2 U1_2.5 | length 435.2
  Top Layer w10: R3_2.2 -1046,1395 -1036,1385 -886,1385 v1(-871,1400)
  Bottom Layer w10: v1(-871,1400) -885.76,1385.24 -885.76,1309.76 -861,1285 U1_2.5
NetR3_3_2: R3_3.2 U1_3.5 | length 435.2
  Top Layer w10: R3_3.2 -393,385 -383,375 -233,375 v1(-218,390)
  Bottom Layer w10: v1(-218,390) -232.76,375.24 -232.76,299.76 -208,275 U1_3.5
NetR3_4_2: R3_4.2 U1_4.5 | length 435.2
  Top Layer w10: R3_4.2 75,385 85,375 235,375 v1(250,390)
  Bottom Layer w10: v1(250,390) 235.24,375.24 235.24,299.76 260,275 U1_4.5
NetR3_5_2: R3_5.2 U1_5.5 | length 435.2
  Top Layer w10: R3_5.2 585,385 595,375 745,375 v1(760,390)
  Bottom Layer w10: v1(760,390) 745.24,375.24 745.24,299.76 770,275 U1_5.5
NetR3_6_2: R3_6.2 U1_6.5 | length 870.5
  Top Layer w10: 1095,385 R3_6.2 1095,385 ; 1095,385 1105,375 ; 1095,385 1105,375 ; 1105,375 1255,375 ; 1105,375 1255,375 ; 1255,375 v1(1270,390) 1255,375
  Bottom Layer w10: 1255.24,299.76 1280,275 ; 1255.24,299.76 1255.24,375.24 ; 1255.24,299.76 1280,275 ; 1255.24,299.76 1255.24,375.24 ; 1255.24,375.24 v1(1270,390) 1255.24,375.24 ; 1280,275 U1_6.5 1280,275
NetR3_7_2: R3_7.2 U1_7.5 | length 435.2
  Top Layer w10: R3_7.2 1605,385 1615,375 1765,375 v1(1780,390)
  Bottom Layer w10: v1(1780,390) 1765.24,375.24 1765.24,299.76 1790,275 U1_7.5
NetR3_8_2: R3_8.2 U1_8.5 | length 435.2
  Top Layer w10: R3_8.2 2115,385 2125,375 2275,375 v1(2290,390)
  Bottom Layer w10: v1(2290,390) 2275.24,375.24 2275.24,299.76 2300,275 U1_8.5
NetR3_9_2: R3_9.2 U1_9.5 | length 435.2
  Top Layer w10: R3_9.2 2625,385 2635,375 2785,375 v1(2800,390)
  Bottom Layer w10: v1(2800,390) 2785.24,375.24 2785.24,299.76 2810,275 U1_9.5
NetR3_10_2: R3_10.2 U1_10.5 | length 435.2
  Top Layer w10: R3_10.2 3135,385 3145,375 3295,375 v1(3310,390)
  Bottom Layer w10: v1(3310,390) 3295.24,375.24 3295.24,299.76 3320,275 U1_10.5
NetR4_1_2: R4_1.2 U1_1.4 | length 338.4
  Top Layer w10: R4_1.2 -1470,265 -1410,325 v1(-1265,325)
  Bottom Layer w10: v1(-1265,325) U1_1.4
NetR4_2_2: R4_2.2 U1_2.4 | length 338.4
  Top Layer w10: R4_2.2 -1061,1275 -1001,1335 v1(-856,1335)
  Bottom Layer w10: v1(-856,1335) U1_2.4
NetR4_3_2: R4_3.2 U1_3.4 | length 338.4
  Top Layer w10: R4_3.2 -408,265 -348,325 v1(-203,325)
  Bottom Layer w10: v1(-203,325) U1_3.4
NetR4_4_2: R4_4.2 U1_4.4 | length 338.4
  Top Layer w10: R4_4.2 60,265 120,325 v1(265,325)
  Bottom Layer w10: v1(265,325) U1_4.4
NetR4_5_2: R4_5.2 U1_5.4 | length 338.4
  Top Layer w10: R4_5.2 570,265 630,325 v1(775,325)
  Bottom Layer w10: v1(775,325) U1_5.4
NetR4_6_2: R4_6.2 U1_6.4 | length 676.7
  Top Layer w10: 1080,265 R4_6.2 1080,265 ; 1080,265 1140,325 ; 1080,265 1140,325 ; 1140,325 v1(1285,325) 1140,325
  Bottom Layer w10: v1(1285,325) U1_6.4 v1(1285,325)
NetR4_7_2: R4_7.2 U1_7.4 | length 338.4
  Top Layer w10: R4_7.2 1590,265 1650,325 v1(1795,325)
  Bottom Layer w10: v1(1795,325) U1_7.4
NetR4_8_2: R4_8.2 U1_8.4 | length 338.4
  Top Layer w10: R4_8.2 2100,265 2160,325 v1(2305,325)
  Bottom Layer w10: v1(2305,325) U1_8.4
NetR4_9_2: R4_9.2 U1_9.4 | length 338.4
  Top Layer w10: R4_9.2 2610,265 2670,325 v1(2815,325)
  Bottom Layer w10: v1(2815,325) U1_9.4
NetR4_10_2: R4_10.2 U1_10.4 | length 338.4
  Top Layer w10: R4_10.2 3120,265 3180,325 v1(3325,325)
  Bottom Layer w10: v1(3325,325) U1_10.4
NetR5_1_2: R5_1.2 U1_1.3 | length 511.4
  Top Layer w10: R5_1.2 -1405,210.35 -1405,277.09 -1377.09,305 -1355,305 -1349,299 v1(-1141,299)
  Bottom Layer w10: U1_1.3 -1177,375 -1141,339 v1(-1141,299)
NetR5_2_2: R5_2.2 U1_2.3 | length 511.4
  Top Layer w10: R5_2.2 -996,1220.35 -996,1287.09 -968.09,1315 -946,1315 -940,1309 v1(-732,1309)
  Bottom Layer w10: U1_2.3 -768,1385 -732,1349 v1(-732,1309)
NetR5_3_2: R5_3.2 U1_3.3 | length 565.5
  Top Layer w10: R5_3.2 -343,210.35 -343,277.09 -315.09,305 -228,305 -213,290 v1(-63,290)
  Bottom Layer w10: U1_3.3 -83,375 -63,355 v1(-63,290)
NetR5_4_2: R5_4.2 U1_4.3 | length 565.5
  Top Layer w10: R5_4.2 125,210.35 125,277.09 152.91,305 240,305 255,290 v1(405,290)
  Bottom Layer w10: U1_4.3 385,375 405,355 v1(405,290)
NetR5_5_2: R5_5.2 U1_5.3 | length 565.5
  Top Layer w10: R5_5.2 635,210.35 635,277.09 662.91,305 750,305 765,290 v1(915,290)
  Bottom Layer w10: U1_5.3 895,375 915,355 v1(915,290)
NetR5_6_2: R5_6.2 U1_6.3 | length 1131
  Top Layer w10: 1145,210.35 1145,277.09 ; 1145,210.35 R5_6.2 1145,210.35 ; 1145,210.35 1145,277.09 ; 1145,277.09 1172.91,305 ; 1145,277.09 1172.91,305 ; 1172.91,305 1260,305 ; 1172.91,305 1260,305 ; 1260,305 1275,290 ; 1260,305 1275,290 ; 1275,290 v1(1425,290) 1275,290
  Bottom Layer w10: 1405,375 1425,355 ; 1405,375 U1_6.3 1405,375 ; 1405,375 1425,355 ; 1425,355 v1(1425,290) 1425,355
NetR5_7_2: R5_7.2 U1_7.3 | length 565.5
  Top Layer w10: R5_7.2 1655,210.35 1655,277.09 1682.91,305 1770,305 1785,290 v1(1935,290)
  Bottom Layer w10: U1_7.3 1915,375 1935,355 v1(1935,290)
NetR5_8_2: R5_8.2 U1_8.3 | length 565.5
  Top Layer w10: R5_8.2 2165,210.35 2165,277.09 2192.91,305 2280,305 2295,290 v1(2445,290)
  Bottom Layer w10: U1_8.3 2425,375 2445,355 v1(2445,290)
NetR5_9_2: R5_9.2 U1_9.3 | length 565.5
  Top Layer w10: R5_9.2 2675,210.35 2675,277.09 2702.91,305 2790,305 2805,290 v1(2955,290)
  Bottom Layer w10: U1_9.3 2935,375 2955,355 v1(2955,290)
NetR5_10_2: R5_10.2 U1_10.3 | length 565.5
  Top Layer w10: R5_10.2 3185,210.35 3185,277.09 3212.91,305 3300,305 3315,290 v1(3465,290)
  Bottom Layer w10: U1_10.3 3445,375 3465,355 v1(3465,290)
NetR6_1_2: R6_1.2 U1_1.2 | length 362
  Top Layer w10: v2(-1280,185) R6_1.2
  Bottom Layer w10: v2(-1280,185) -1315,220 -1315,405 -1295,425 U1_1.2
NetR6_2_2: R6_2.2 U1_2.2 | length 362
  Top Layer w10: v2(-871,1195) R6_2.2
  Bottom Layer w10: v2(-871,1195) -906,1230 -906,1415 -886,1435 U1_2.2
NetR6_3_2: R6_3.2 U1_3.2 | length 362
  Top Layer w10: v2(-218,185) R6_3.2
  Bottom Layer w10: v2(-218,185) -253,220 -253,405 -233,425 U1_3.2
NetR6_4_2: R6_4.2 U1_4.2 | length 362
  Top Layer w10: v2(250,185) R6_4.2
  Bottom Layer w10: v2(250,185) 215,220 215,405 235,425 U1_4.2
NetR6_5_2: R6_5.2 U1_5.2 | length 362
  Top Layer w10: v2(760,185) R6_5.2
  Bottom Layer w10: v2(760,185) 725,220 725,405 745,425 U1_5.2
NetR6_6_2: R6_6.2 U1_6.2 | length 724
  Top Layer w10: v2(1270,185) R6_6.2 v2(1270,185)
  Bottom Layer w10: 1235,220 v2(1270,185) 1235,220 ; 1235,220 1235,405 ; 1235,220 1235,405 ; 1235,405 1255,425 ; 1235,405 1255,425 ; 1255,425 U1_6.2 1255,425
NetR6_7_2: R6_7.2 U1_7.2 | length 362
  Top Layer w10: v2(1780,185) R6_7.2
  Bottom Layer w10: v2(1780,185) 1745,220 1745,405 1765,425 U1_7.2
NetR6_8_2: R6_8.2 U1_8.2 | length 362
  Top Layer w10: v2(2290,185) R6_8.2
  Bottom Layer w10: v2(2290,185) 2255,220 2255,405 2275,425 U1_8.2
NetR6_9_2: R6_9.2 U1_9.2 | length 362
  Top Layer w10: v2(2800,185) R6_9.2
  Bottom Layer w10: v2(2800,185) 2765,220 2765,405 2785,425 U1_9.2
NetR6_10_2: R6_10.2 U1_10.2 | length 362
  Top Layer w10: v2(3310,185) R6_10.2
  Bottom Layer w10: v2(3310,185) 3275,220 3275,405 3295,425 U1_10.2
NetR7_1_2: R7_1.2 U1_1.1 | length 155.9
  Top Layer w10: v1(-1275,475) -1245,505 R7_1.2
  Bottom Layer w10: v1(-1275,475) U1_1.1
NetR7_2_2: R7_2.2 U1_2.1 | length 155.9
  Top Layer w10: v1(-866,1485) -836,1515 R7_2.2
  Bottom Layer w10: v1(-866,1485) U1_2.1
NetR7_3_2: R7_3.2 U1_3.1 | length 155.9
  Top Layer w10: v1(-213,475) -183,505 R7_3.2
  Bottom Layer w10: v1(-213,475) U1_3.1
NetR7_4_2: R7_4.2 U1_4.1 | length 155.9
  Top Layer w10: v1(255,475) 285,505 R7_4.2
  Bottom Layer w10: v1(255,475) U1_4.1
NetR7_5_2: R7_5.2 U1_5.1 | length 155.9
  Top Layer w10: v1(765,475) 795,505 R7_5.2
  Bottom Layer w10: v1(765,475) U1_5.1
NetR7_6_2: R7_6.2 U1_6.1 | length 311.9
  Top Layer w10: 1305,505 v1(1275,475) 1305,505 ; 1305,505 R7_6.2 1305,505
  Bottom Layer w10: v1(1275,475) U1_6.1 v1(1275,475)
NetR7_7_2: R7_7.2 U1_7.1 | length 155.9
  Top Layer w10: v1(1785,475) 1815,505 R7_7.2
  Bottom Layer w10: v1(1785,475) U1_7.1
NetR7_8_2: R7_8.2 U1_8.1 | length 155.9
  Top Layer w10: v1(2295,475) 2325,505 R7_8.2
  Bottom Layer w10: v1(2295,475) U1_8.1
NetR7_9_2: R7_9.2 U1_9.1 | length 155.9
  Top Layer w10: v1(2805,475) 2835,505 R7_9.2
  Bottom Layer w10: v1(2805,475) U1_9.1
NetR7_10_2: R7_10.2 U1_10.1 | length 155.9
  Top Layer w10: v1(3315,475) 3345,505 R7_10.2
  Bottom Layer w10: v1(3315,475) U1_10.1
NetR8_1_2: R8_1.2 U1_1.15 | length 88.9
  Bottom Layer w10: U1_1.15 v2(-1375,425)
NetR8_2_2: R8_2.2 U1_2.15 | length 88.9
  Bottom Layer w10: U1_2.15 v2(-966,1435)
NetR8_3_2: R8_3.2 U1_3.15 | length 88.9
  Bottom Layer w10: U1_3.15 v2(-313,425)
NetR8_4_2: R8_4.2 U1_4.15 | length 88.9
  Bottom Layer w10: U1_4.15 v2(155,425)
NetR8_5_2: R8_5.2 U1_5.15 | length 88.9
  Bottom Layer w10: U1_5.15 v2(665,425)
NetR8_6_2: R8_6.2 U1_6.15 | length 177.7
  Bottom Layer w10: U1_6.15 v2(1175,425) U1_6.15
NetR8_7_2: R8_7.2 U1_7.15 | length 88.9
  Bottom Layer w10: U1_7.15 v2(1685,425)
NetR8_8_2: R8_8.2 U1_8.15 | length 88.9
  Bottom Layer w10: U1_8.15 v2(2195,425)
NetR8_9_2: R8_9.2 U1_9.15 | length 88.9
  Bottom Layer w10: U1_9.15 v2(2705,425)
NetR8_10_2: R8_10.2 U1_10.15 | length 88.9
  Bottom Layer w10: U1_10.15 v2(3215,425)
NetU1_1_9: U1_1.9 U1_2.14 | length 495.1
  Bottom Layer w10: U1_1.9 -1285,125 -1250,90 -1155,90 -1098,147 ; -1146,1385 U1_2.14
NetU1_1_14: pad.9 U1_1.14 | length 407.8
  Bottom Layer w10: -1626.24,238.76 -1626.24,367.45 ; -1608,147 -1608,335 ; pad.9@-1555,375 U1_1.14
NetU1_2_9: U1_2.9 U1_3.14 | length 752.7
  Bottom Layer w10: U1_2.9 -876,1135 -841,1100 -746,1100 -689,1157 ; -546,147 -546,335 -506,375 U1_3.14
NetU1_3_9: U1_3.9 U1_4.14 | length 642.3
  Bottom Layer w10: U1_3.9 -223,125 -188,90 -93,90 -13.24,169.76 -13.24,314.76 ; 5,375 U1_4.14
NetU1_4_9: U1_4.9 U1_5.14 | length 897.9
  Bottom Layer w10: U1_4.9 245,125 280,90 375,90 454.76,169.76 454.76,314.76 ; U1_5.14 515,375 ; 454.76,314.76 515,375 ; 454.76,314.76 515,375 ; 454.76,314.76 515,375
NetU1_5_9: U1_5.9 U1_6.14 | length 1129.4
  Bottom Layer w10: U1_5.9 755,125 790,90 885,90 964.76,169.76 964.76,314.76 ; 964.76,314.76 1025,375 ; 964.76,314.76 1025,375 ; 964.76,314.76 1025,375 ; 964.76,314.76 1025,375 ; 964.76,314.76 1025,375 ; 1025,375 U1_6.14 1025,375
NetU1_6_9: U1_6.9 U1_7.14 | length 1564.2
  Bottom Layer w10: U1_7.14 1535,375 ; 1265,125 1300,90 ; 1265,125 U1_6.9 1265,125 ; 1265,125 1300,90 ; 1300,90 1395,90 ; 1300,90 1395,90 ; 1395,90 1474.76,169.76 ; 1395,90 1474.76,169.76 ; 1474.76,169.76 1474.76,314.76 ; 1474.76,169.76 1474.76,314.76 ; 1474.76,314.76 1535,375 ; 1474.76,314.76 1535,375 ; 1474.76,314.76 1535,375 ; 1474.76,314.76 1535,375
NetU1_7_9: U1_7.9 U1_8.14 | length 897.9
  Bottom Layer w10: U1_7.9 1775,125 1810,90 1905,90 1984.76,169.76 1984.76,314.76 ; U1_8.14 2045,375 ; 1984.76,314.76 2045,375 ; 1984.76,314.76 2045,375 ; 1984.76,314.76 2045,375
NetU1_8_9: U1_8.9 U1_9.14 | length 983
  Bottom Layer w10: U1_8.9 2285,125 2320,90 2415,90 2494.76,169.76 2494.76,314.76 ; U1_9.14 2555,375 ; 2494.76,314.76 2555,375 ; 2494.76,314.76 2555,375 ; 2494.76,314.76 2555,375 ; 2494.76,314.76 2555,375
NetU1_9_9: U1_9.9 U1_10.14 | length 897.9
  Bottom Layer w10: U1_9.9 2795,125 2830,90 2925,90 3004.76,169.76 3004.76,314.76 ; U1_10.14 3065,375 ; 3004.76,314.76 3065,375 ; 3004.76,314.76 3065,375 ; 3004.76,314.76 3065,375
NetU1_10_9: U1_10.9
SHCP: pad.11 U1_1.11 U1_2.11 U1_3.11 U1_4.11 U1_5.11 U1_6.11 U1_7.11 U1_8.11 U1_9.11 U1_10.11 | length 4423.5
  Top Layer w10: -1555,240 v2(-1533,218) ; v1(-1365,225) -1350,240 -1045,240 ; v1(-956,1235) -941,1250 -636,1250 v2(-614,1228) ; -493,240 v2(-471,218) ; v1(-303,225) -288,240 ; v1(165,225) 180,240 500,240 v1(515,225) ; v1(675,225) 690,240 1010,240 v1(1025,225) ; v1(1185,225) 1200,240 1520,240 v1(1535,225) ; v1(1695,225) 1710,240 2030,240 v1(2045,225) ; v1(2205,225) 2220,240 2540,240 v1(2555,225) ; v1(2715,225) 2730,240 3050,240 v1(3065,225)
  Bottom Layer w10: U1_1.11@-1505,225 U1_1.11 v1(-1365,225) ; U1_2.11@-1096,1235 U1_2.11 v1(-956,1235) ; v2(-614,1228) v2@-607,1235 ; v2(-471,218) -464,225 U1_3.11 v1(-303,225) ; 5,225 U1_4.11 v1(165,225) ; v1(515,225) v1(675,225) ; v1(1025,225) v1(1185,225) ; v1(1535,225) v1(1695,225) ; v1(2045,225) v1(2205,225) ; v1(2555,225) v1(2715,225) ; v1(3065,225) U1_10.11
STCP: pad.10 U1_1.12 U1_2.12 U1_3.12 U1_4.12 U1_5.12 U1_6.12 U1_7.12 U1_8.12 U1_9.12 U1_10.12 | length 4817.1
  Top Layer w10: v1(-1365,275) -1350,260 -1030,260 ; v1(-956,1285) -941,1270 -621,1270 ; v2@-478,260 -473,265 v2(-473,261) ; v1(-303,275) -288,260 32,260 37,265 v2(37,261) ; v1(165,275) 180,260 500,260 v1(515,275) ; v1(675,275) 690,260 1010,260 v1(1025,275) ; v1(1185,275) 1200,260 1520,260 v1(1535,275) ; v1(1695,275) 1710,260 2030,260 v1(2045,275) ; v1(2205,275) 2220,260 2540,260 v1(2555,275) ; v1(2715,275) 2730,260 3050,260 v1(3065,275)
  Bottom Layer w10: pad.10@-1555,275 U1_1.12 v1(-1365,275) ; -1146,1285 U1_2.12 v1(-956,1285) ; v2(-473,261) -459,275 U1_3.12 v1(-303,275) ; 5,275 U1_4.12 v1(165,275) ; v2(37,261) U1_4.12@51,275 ; v1(515,275) v1(675,275) ; v1(1025,275) v1(1185,275) ; v1(1535,275) v1(1695,275) ; v1(2045,275) v1(2205,275) ; v1(2555,275) v1(2715,275) ; v1(3065,275) U1_10.12
  other v2: -1535,261 -1126,1271

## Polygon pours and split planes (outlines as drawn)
GND on Bottom Layer "Bottom Layer-No Net" (solid, shelved, pour order 0): -1700,700 3606,700 3606,-100 -1700,-100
